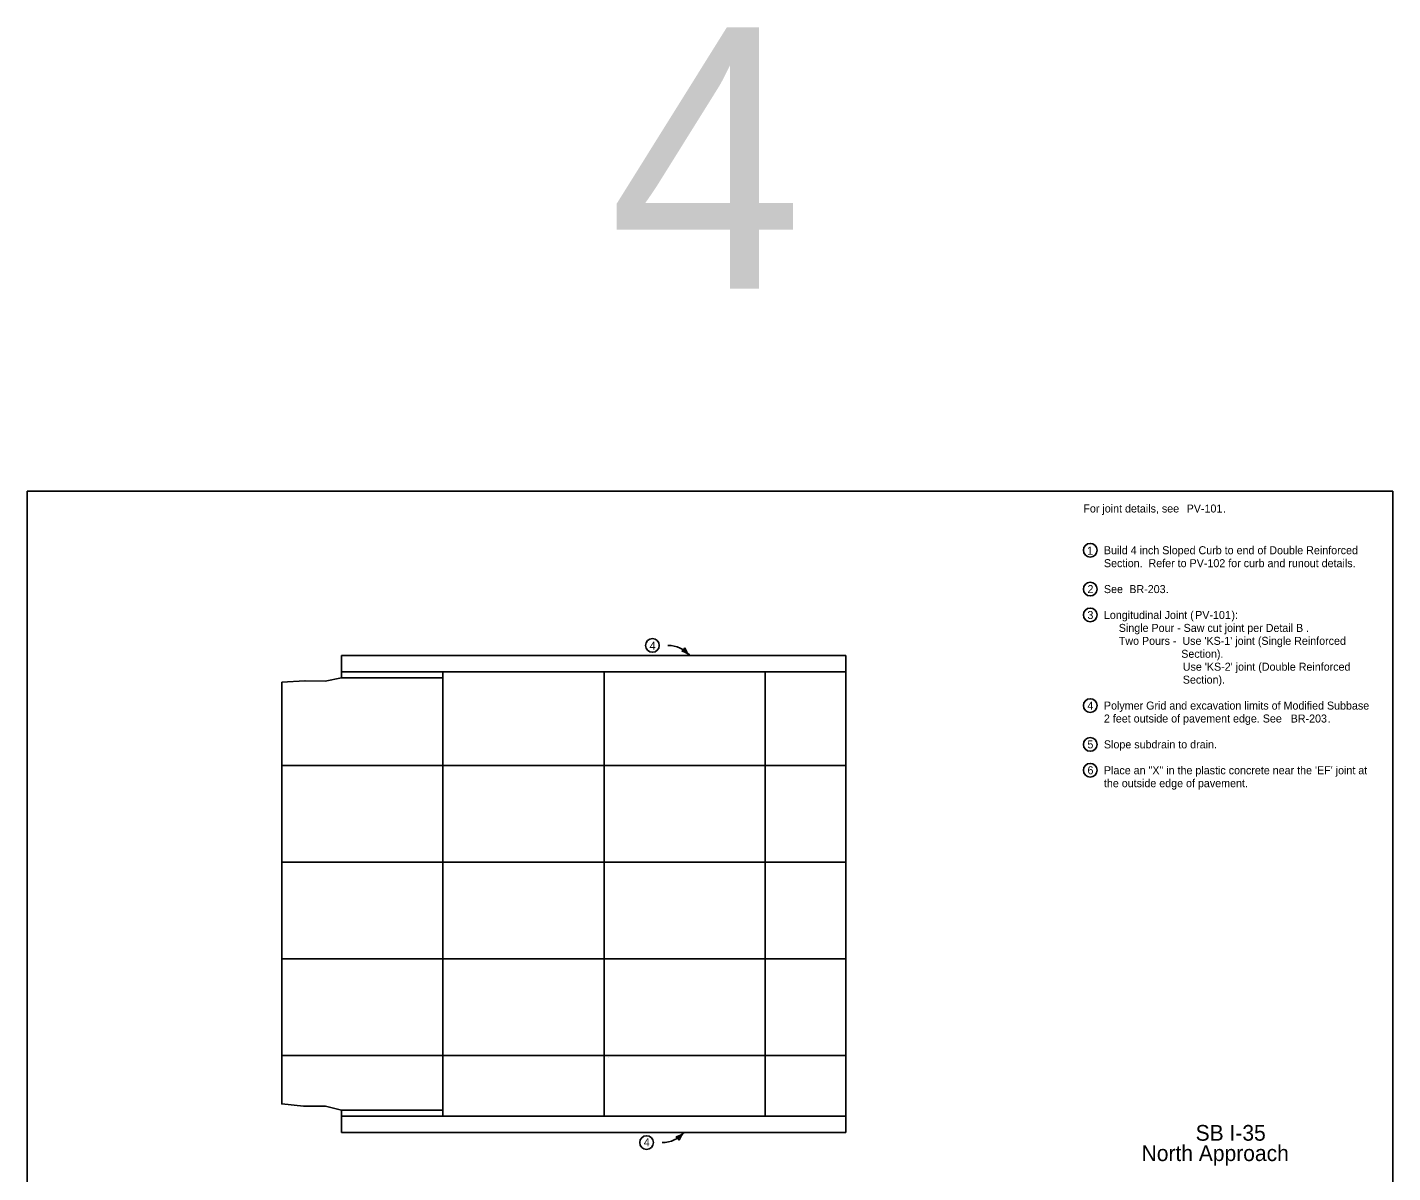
# Model space of a CAD drawing. Extents: x 10045 to 81668, y 6370 to 11018.
# Drawn here: x 20933 to 24068, y 8380 to 11009 of the extents above; entities that cross this region are included whole.
import ezdxf

# ---------------------------------------------------------------- set-up
doc = ezdxf.new("R2010")
doc.units = 0
for name, color, linetype in [('Alignment', 7, 'Continuous'), ('Bridge', 7, 'Continuous'), ('Default', 7, 'Continuous'), ('dsnStdLineWork', 7, 'Continuous'), ('LaneLine', 7, 'Continuous'), ('Level 5', 7, 'Continuous'), ('PC_APPROACH', 7, 'Continuous'), ('SheetText', 7, 'Continuous'), ('TextAlignmentLrg', 7, 'Continuous'), ('TextAlignmentSml', 7, 'Continuous')]:
    doc.layers.add(name, color=color, linetype=linetype)

msp = doc.modelspace()

# ---------------------------------------------------------------- linework, layer by layer
at = {"layer": 'Alignment'}
for centre, start, end in [((22403.3, 9523.4), 40.5607, 90), ((22403.3, 9523.4), 40.5607, 90), ((22390.1, 8515.9), 270, 319.4393), ((22390.1, 8515.9), 270, 319.4393)]:
    msp.add_arc(centre, 66.8, start, end, dxfattribs=at)
at = {"layer": 'Default'}
msp.add_line((22266, 8644.6), (22266, 8644.6), dxfattribs=at)
at = {"layer": 'dsnStdLineWork'}
for p, q in [((21654, 9566.8), (21886.9, 9566.8)), ((21654, 9566.8), (21654, 9529.8)), ((21886.9, 9566.8), (22812, 9566.8)), ((22812, 9566.8), (22812, 9529.8)), ((21653.9, 8509.5), (21653.9, 8472.5)), ((22811.9, 8509.5), (22811.9, 8472.5)), ((21653.9, 8472.5), (21886.8, 8472.5)), ((21886.8, 8472.5), (22811.9, 8472.5))]:
    msp.add_line(p, q, dxfattribs=at)
for points in [[(21516.8, 9505.9), (21516.7, 8537.6), (21566.8, 8532.6), (21616.9, 8532.6), (21653.9, 8523.3), (21653.9, 8509.5), (21886.8, 8509.5), (21886.9, 9529.8), (21654, 9529.8), (21653.6, 9515.9), (21616.3, 9507.9), (21569.9, 9509.3), (21569.9, 9509.3)], [(22256.9, 9529.8), (22256.8, 8509.5), (22256.8, 8509.5), (22811.9, 8509.5), (22812, 9529.8)]]:
    msp.add_lwpolyline(points, close=True, dxfattribs=at)
for centre in [(23373, 9808.8), (23373, 9719.6), (23373, 9660.2), (22367.7, 9590.2), (22367.7, 9590.2), (23373, 9452.2), (23373, 9363.1), (23373, 9303.7), (22354.5, 8449.1), (22354.5, 8449.1)]:
    msp.add_circle(centre, 15.7, dxfattribs=at)
for centre, radius, start, end in [((22426.8, 9592.1), 17.1, 299.4947, 334.9614), ((22426.8, 9592.1), 17.1, 299.4947, 334.9614), ((22423.9, 9534.2), 44.4, 47.2281, 75.3006), ((22423.9, 9534.2), 44.4, 47.2281, 75.3006), ((22484.2, 9599.4), 44.4, 199.1556, 227.2281), ((22484.2, 9599.4), 44.4, 199.1556, 227.2281), ((22410.7, 8505.1), 44.4, 284.6994, 312.7719), ((22410.7, 8505.1), 44.4, 284.6994, 312.7719), ((22471, 8439.9), 44.4, 132.7719, 160.8444), ((22471, 8439.9), 44.4, 132.7719, 160.8444), ((22413.5, 8447.2), 17.1, 25.0386, 60.5053), ((22413.5, 8447.2), 17.1, 25.0386, 60.5053)]:
    msp.add_arc(centre, radius, start, end, dxfattribs=at)
at = {"layer": 'LaneLine'}
msp.add_lwpolyline([(21516.8, 9505.9), (21516.7, 8537.6), (21566.8, 8532.6), (21616.9, 8532.6), (21653.9, 8523.3), (21653.9, 8509.5), (22256.8, 8509.5), (22256.9, 9529.8), (21654, 9529.8), (21653.6, 9515.9), (21616.3, 9507.9), (21569.9, 9509.3)], close=True, dxfattribs=at)
at = {"layer": 'Level 5'}
msp.add_lwpolyline([(20932.5, 9944), (24067.5, 9944), (24067.5, 7924), (20932.5, 7924)], close=True, dxfattribs=at)
at = {"layer": 'PC_APPROACH'}
for p, q in [((21516.7, 8537.6), (21516.8, 9505.9)), ((21653.6, 9515.9), (21654, 9529.8)), ((21886.9, 9529.8), (22812, 9529.8)), ((22811.9, 8509.5), (22812, 9529.8)), ((21886.8, 8509.5), (22811.9, 8509.5))]:
    msp.add_line(p, q, dxfattribs=at)
for points in [[(21516.8, 9505.9), (21569.9, 9509.3), (21616.3, 9507.9), (21653.6, 9515.9)], [(21516.7, 8537.6), (21566.8, 8532.6), (21616.9, 8532.6), (21653.9, 8523.3), (21653.9, 8509.5)]]:
    msp.add_lwpolyline(points, dxfattribs=at)
at = {"layer": 'TextAlignmentLrg'}
for p, q in [((21886.8, 8509.5), (21886.9, 9529.8)), ((22256.8, 8509.5), (22256.9, 9529.8)), ((22626.9, 8509.5), (22627, 9529.8)), ((21516.7, 9314.7), (22812, 9314.7)), ((21516.7, 9092.7), (22812, 9092.7)), ((21516.7, 8870.7), (22812, 8870.7)), ((21516.7, 8648.6), (22811.9, 8648.6))]:
    msp.add_line(p, q, dxfattribs=at)
at = {"layer": 'TextAlignmentSml'}
for p, q in [((21654, 9529.8), (21886.9, 9529.8)), ((21654, 9515.9), (21886.9, 9515.9)), ((21886.9, 9515.9), (21886.9, 9529.8)), ((21653.9, 8523.3), (21886.8, 8523.3)), ((21653.9, 8509.5), (21886.8, 8509.5)), ((21886.8, 8523.3), (21886.8, 8509.5))]:
    msp.add_line(p, q, dxfattribs=at)

# ---------------------------------------------------------------- texts
at = {"layer": 'Alignment'}
for s, height, p in [('For joint details, see ', 18.375, (23357.3, 9895.4)), ('PV-101', 18.37, (23594.5, 9895.4)), ('PV-101', 18.37, (23594.5, 9895.4)), ('.', 18.4, (23677.7, 9895.4)), ('1', 18.4, (23365.8, 9798.5)), ('Build 4 inch Sloped Curb to end of Double Reinforced', 18.375, (23404.5, 9799.6)), ('Section.  Refer to PV-102 for curb and runout details.', 18.375, (23404.5, 9769.9)), ('2', 18.4, (23366.8, 9710.4)), ('See ', 18.37, (23404.5, 9710.4)), ('BR-203.', 18.37, (23462.8, 9710.4)), ('.', 18.4, (23547.4, 9710.4)), ('3', 18.4, (23366.6, 9651)), ('Longitudinal Joint (', 18.375, (23404.5, 9651)), ('PV-101', 18.37, (23614, 9651)), ('PV-101', 18.37, (23614, 9651)), ('):', 18.37, (23697.3, 9651)), ('     Single Pour - Saw cut joint per Detail B .', 18.375, (23404.5, 9621.3)), ('4', 18.4, (22361.3, 9580.3)), ('4', 18.4, (22361.3, 9580.3)), ("     Two Pours -  Use 'KS-1' joint (Single Reinforced", 18.375, (23404.5, 9591.6)), ('                          Section).', 18.375, (23404.5, 9561.9)), ("     Use 'KS-2' joint (Double Reinforced", 18.375, (23551.5, 9532.2)), ('     Section).', 18.375, (23551.5, 9502.5)), ('4', 18.4, (23366.6, 9443)), ('Polymer Grid and excavation limits of Modified Subbase', 18.375, (23404.5, 9443)), ('2 feet outside of pavement edge. See ', 18.375, (23404.5, 9413.3)), ('BR-203', 18.37, (23833.3, 9413.3)), ('.', 18.4, (23917.9, 9413.3)), ('5', 18.4, (23366.6, 9353.9)), ('Slope subdrain to drain.', 18.375, (23404.5, 9353.9)), ('6', 18.4, (23366.8, 9294.5)), ('Place an "X" in the plastic concrete near the \'EF\' joint at', 18.375, (23404.5, 9294.5)), ('the outside edge of pavement.', 18.375, (23404.5, 9264.8)), ('4', 18.4, (22348.1, 8440.6)), ('4', 18.4, (22348.1, 8440.6))]:
    msp.add_text(s, height=height, dxfattribs=at).set_placement(p)
at = {"layer": 'Bridge'}
for s, height, p in [('SB I-35', 36.09, (23615.1, 8453.3)), ('North Approach', 36.086, (23491, 8406.6))]:
    msp.add_text(s, height=height, dxfattribs=at).set_placement(p)
at = {"layer": 'SheetText'}
msp.add_text('4', height=600, dxfattribs=at).set_placement((22267.6, 10409.2))

doc.saveas('drawing.dxf')
